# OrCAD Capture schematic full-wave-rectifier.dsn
size A; title: Full Wave Rectifier
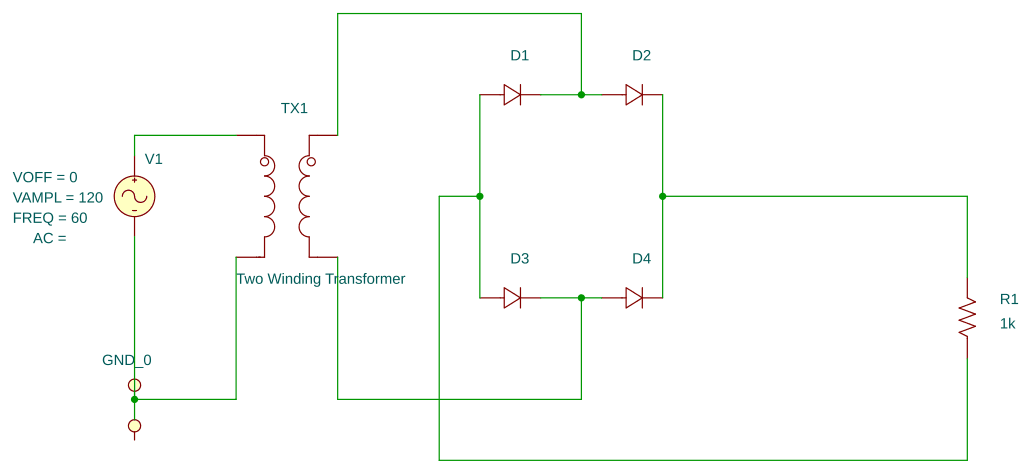
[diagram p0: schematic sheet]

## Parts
D1  Dbreak
D2  Dbreak
D3  Dbreak
D4  Dbreak
R1  1k  [AXRC05]
TX1  Two Winding Transformer
V1  VSIN

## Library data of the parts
D1-D4 = Dbreak
R1 = R
TX1 = ST: AppProp: modelname=ST_Model,LP1=1m,RP1=10m,Rs1=10m,N=0.1,LI=100n
V1 = VSIN: FREQ: 60; VAMPL: 120; VOFF: 0

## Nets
0: TX1.2 V1.2(-)
N20822: D1.1(2) D2.0(1) TX1.3
N20876: D1.0(1) D3.0(1) R1.1
N20888: D2.1(2) D4.1(2) R1.2
N20892: TX1.1 V1.1(+)
N20998: D3.1(2) D4.0(1) TX1.4
